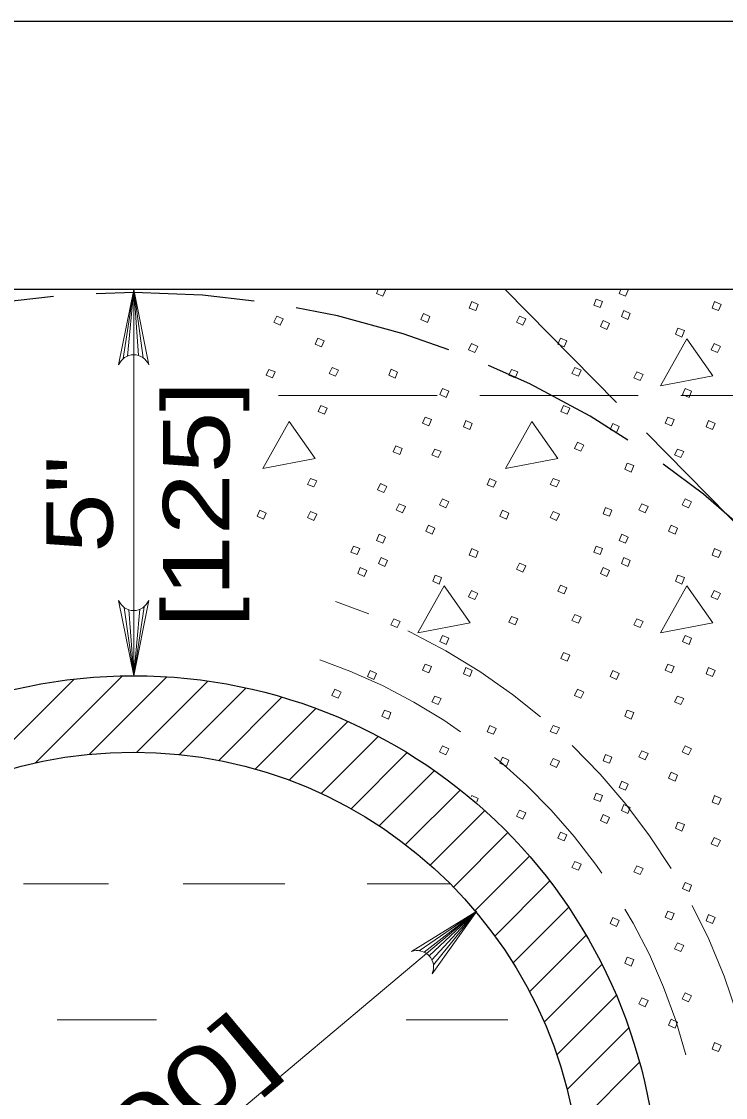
# Model space of a CAD drawing. Extents: x 1036.7 to 1070.7, y 883.9 to 905.9.
# Drawn here: x 1060.088 to 1061.74, y 889.969 to 892.494 of the extents above; entities that cross this region are included whole.
import ezdxf
from ezdxf.enums import TextEntityAlignment as Align

# ---------------------------------------------------------------- set-up
doc = ezdxf.new("R2010")
doc.units = 0
doc.header["$LTSCALE"] = 0.062
doc.linetypes.add('LONG_DASHED', pattern=[7.5, 6, -1.5])
doc.layers.add('1', color=7, linetype='Continuous', lineweight=13)

msp = doc.modelspace()

# ---------------------------------------------------------------- linework, layer by layer
at = {"layer": '1', "lineweight": 25}
for p, q in [((1062.47975, 892.494), (1058.22342, 892.494)), ((1062.47975, 891.86492), (1058.22342, 891.86492))]:
    msp.add_line(p, q, dxfattribs=at)
at = {"layer": '1'}
for p, q in [((1060.32675, 891.70283), (1060.35158, 891.86492)), ((1060.33717, 891.70892), (1060.35158, 891.86492)), ((1060.35158, 891.86492), (1060.35158, 891.54058)), ((1060.35158, 891.71175), (1060.35158, 891.86492)), ((1060.36292, 891.71017), (1060.35158, 891.86492)), ((1060.374, 891.70467), (1060.35158, 891.86492)), ((1060.35158, 890.95858), (1060.35158, 891.54058)), ((1060.32917, 891.11883), (1060.35158, 890.95858)), ((1060.37633, 891.12067), (1060.35158, 890.95858)), ((1060.34025, 891.11333), (1060.35158, 890.95858)), ((1060.36592, 891.11458), (1060.35158, 890.95858)), ((1060.35158, 891.11175), (1060.35158, 890.95858)), ((1059.96908, 890.70792), (1060.21167, 890.95058)), ((1060.12142, 890.75425), (1060.32483, 890.95767)), ((1060.24758, 890.77442), (1060.42908, 890.95592)), ((1060.35858, 890.77933), (1060.52533, 890.94608)), ((1060.459, 890.77375), (1060.615, 890.92975)), ((1060.55125, 890.76), (1060.69933, 890.90808)), ((1060.63675, 890.7395), (1060.77892, 890.88167)), ((1060.71667, 890.71333), (1060.85433, 890.851)), ((1060.7915, 890.68225), (1060.92558, 890.81633)), ((1060.86175, 890.6465), (1060.993, 890.77775)), ((1060.92775, 890.60642), (1061.057, 890.73558)), ((1060.98967, 890.56233), (1061.1175, 890.69017)), ((1061.14433, 890.67508), (1061.14525, 890.67725)), ((1061.04783, 890.5145), (1061.17483, 890.6415)), ((1061.102, 890.46275), (1061.229, 890.58967)), ((1061.1525, 890.40717), (1061.27992, 890.53467)), ((1060.09275, 890.4705), (1060.29267, 890.4705)), ((1060.46758, 890.4705), (1060.70617, 890.4705)), ((1060.8995, 890.4705), (1061.09433, 890.4705)), ((1061.19917, 890.34783), (1061.32775, 890.47642)), ((1061.24192, 890.2845), (1061.37233, 890.41492)), ((1059.55425, 889.06067), (1061.15725, 890.40575)), ((1061.02167, 890.31342), (1061.15725, 890.40575)), ((1061.03325, 890.31), (1061.15725, 890.40575)), ((1061.04508, 890.30142), (1061.15725, 890.40575)), ((1061.05158, 890.292), (1061.15725, 890.40575)), ((1061.05517, 890.28017), (1061.15725, 890.40575)), ((1061.2805, 890.21717), (1061.41317, 890.34975)), ((1061.31483, 890.14542), (1061.45025, 890.28083)), ((1061.34442, 890.069), (1061.48375, 890.20833)), ((1060.17158, 890.15083), (1060.40508, 890.15083)), ((1060.99117, 890.15083), (1061.22967, 890.15083)), ((1061.36875, 889.98733), (1061.51317, 890.13175)), ((1061.38708, 889.89967), (1061.53817, 890.05075))]:
    msp.add_line(p, q, dxfattribs=at)
at = {"layer": '1', "linetype": 'LONG_DASHED'}
for p, q in [((1061.22375, 891.86492), (1062.47975, 890.5895)), ((1062.47975, 891.61667), (1060.64108, 891.61667))]:
    msp.add_line(p, q, dxfattribs=at)
at = {"layer": '1'}
for points in [[(1060.31617, 891.68792), (1060.35158, 891.86492), (1060.387, 891.68792)], [(1060.93933, 891.86492), (1060.94233, 891.8635), (1060.93633, 891.8495), (1060.92133, 891.8555), (1060.92508, 891.86492)], [(1061.50908, 891.86492), (1061.51208, 891.8635), (1061.50608, 891.8495), (1061.49108, 891.8555), (1061.49483, 891.86492)], [(1060.387, 891.13558), (1060.35158, 890.95858), (1060.31617, 891.13558)], [(1061.14525, 890.67725), (1061.16025, 890.67025), (1061.157, 890.66267)], [(1061.0035, 890.31108), (1061.15725, 890.40575), (1061.05175, 890.25925)]]:
    msp.add_lwpolyline(points, dxfattribs=at)
for points in [[(1061.14525, 891.83658), (1061.16025, 891.82958), (1061.15425, 891.81558), (1061.13925, 891.82158)], [(1061.43717, 891.8425), (1061.45208, 891.83658), (1061.44617, 891.82258), (1061.43117, 891.82858)], [(1061.715, 891.83658), (1061.73, 891.82958), (1061.724, 891.81558), (1061.709, 891.82158)], [(1060.6875, 891.80258), (1060.7025, 891.79658), (1060.6955, 891.78158), (1060.6805, 891.78858)], [(1061.03183, 891.80842), (1061.04683, 891.80142), (1061.04083, 891.78742), (1061.02583, 891.79442)], [(1061.25725, 891.80258), (1061.27217, 891.79658), (1061.26525, 891.78158), (1061.25025, 891.78858)], [(1061.50208, 891.81558), (1061.51708, 891.80858), (1061.51108, 891.79458), (1061.49608, 891.80158)], [(1061.45308, 891.79258), (1061.46808, 891.78558), (1061.46208, 891.77158), (1061.44717, 891.77858)], [(1061.629, 891.77458), (1061.644, 891.76858), (1061.638, 891.75358), (1061.62308, 891.76058)], [(1060.78342, 891.75058), (1060.79842, 891.74458), (1060.79242, 891.73058), (1060.77742, 891.73658)], [(1061.35317, 891.75058), (1061.36817, 891.74458), (1061.36217, 891.73058), (1061.34717, 891.73658)], [(1061.65, 891.74958), (1061.58808, 891.63867), (1061.711, 891.66267)], [(1061.14425, 891.73858), (1061.15925, 891.73158), (1061.15225, 891.71758), (1061.13725, 891.72358)], [(1061.714, 891.73858), (1061.729, 891.73158), (1061.722, 891.71758), (1061.707, 891.72358)], [(1060.6685, 891.67767), (1060.6835, 891.67167), (1060.6775, 891.65767), (1060.6625, 891.66367)], [(1060.81742, 891.68167), (1060.83242, 891.67567), (1060.82542, 891.66167), (1060.81042, 891.66767)], [(1060.95608, 891.67775), (1060.97108, 891.67075), (1060.96508, 891.65675), (1060.95008, 891.66375)], [(1061.23825, 891.67767), (1061.25325, 891.67167), (1061.24725, 891.65767), (1061.23225, 891.66367)], [(1061.38717, 891.68167), (1061.40217, 891.67567), (1061.39517, 891.66167), (1061.38017, 891.66767)], [(1061.53208, 891.67167), (1061.54708, 891.66567), (1061.54008, 891.65167), (1061.52508, 891.65767)], [(1061.07633, 891.63267), (1061.09133, 891.62667), (1061.08533, 891.61167), (1061.07033, 891.61867)], [(1061.646, 891.63267), (1061.661, 891.62667), (1061.655, 891.61167), (1061.64, 891.61867)], [(1060.79042, 891.59267), (1060.80542, 891.58667), (1060.79942, 891.57267), (1060.78442, 891.57867)], [(1061.36017, 891.59267), (1061.37517, 891.58667), (1061.36917, 891.57267), (1061.35417, 891.57867)], [(1060.7165, 891.55567), (1060.6545, 891.44475), (1060.77742, 891.46875)], [(1061.03533, 891.56567), (1061.05033, 891.55967), (1061.04433, 891.54475), (1061.02933, 891.55167)], [(1061.13125, 891.55767), (1061.14625, 891.55067), (1061.14025, 891.53675), (1061.12525, 891.54275)], [(1061.28617, 891.55567), (1061.22425, 891.44475), (1061.34717, 891.46875)], [(1061.47608, 891.55067), (1061.49108, 891.54375), (1061.48508, 891.52975), (1061.47008, 891.53675)], [(1061.60508, 891.56567), (1061.62008, 891.55967), (1061.61408, 891.54475), (1061.59908, 891.55167)], [(1061.701, 891.55767), (1061.716, 891.55067), (1061.71, 891.53675), (1061.695, 891.54275)], [(1060.96692, 891.498), (1060.98192, 891.492), (1060.97592, 891.47808), (1060.96092, 891.48408)], [(1061.39317, 891.50675), (1061.40817, 891.49975), (1061.40117, 891.48575), (1061.38617, 891.49175)], [(1061.05833, 891.49075), (1061.07333, 891.48475), (1061.06633, 891.47075), (1061.05133, 891.47675)], [(1061.628, 891.49075), (1061.643, 891.48475), (1061.636, 891.47075), (1061.62108, 891.47675)], [(1061.51008, 891.45775), (1061.52508, 891.45175), (1061.51908, 891.43675), (1061.50408, 891.44375)], [(1060.76642, 891.42175), (1060.78142, 891.41575), (1060.77442, 891.40183), (1060.75942, 891.40775)], [(1061.18725, 891.42175), (1061.20225, 891.41475), (1061.19625, 891.40083), (1061.18125, 891.40675)], [(1061.33617, 891.42175), (1061.35117, 891.41575), (1061.34417, 891.40183), (1061.32917, 891.40775)], [(1060.93058, 891.40983), (1060.94558, 891.40283), (1060.93858, 891.38883), (1060.92358, 891.39483)], [(1061.07633, 891.37383), (1061.09133, 891.36683), (1061.08433, 891.35283), (1061.06933, 891.35983)], [(1061.646, 891.37383), (1061.661, 891.36683), (1061.654, 891.35283), (1061.639, 891.35983)], [(1060.6475, 891.34683), (1060.6625, 891.33983), (1060.6565, 891.32583), (1060.6415, 891.33283)], [(1060.97433, 891.36183), (1060.98933, 891.35583), (1060.98233, 891.34083), (1060.96733, 891.34783)], [(1061.21725, 891.34683), (1061.23225, 891.33983), (1061.22625, 891.32583), (1061.21125, 891.33283)], [(1061.45908, 891.35383), (1061.47408, 891.34683), (1061.46808, 891.33283), (1061.45308, 891.33883)], [(1061.54408, 891.36183), (1061.55908, 891.35583), (1061.55208, 891.34083), (1061.53708, 891.34783)], [(1060.76642, 891.34383), (1060.78142, 891.33783), (1060.77442, 891.32283), (1060.75942, 891.32983)], [(1061.33617, 891.34383), (1061.35117, 891.33783), (1061.34417, 891.32283), (1061.32917, 891.32983)], [(1061.04333, 891.31183), (1061.05833, 891.30483), (1061.05233, 891.29083), (1061.03733, 891.29783)], [(1061.61308, 891.31183), (1061.628, 891.30483), (1061.62208, 891.29083), (1061.60708, 891.29783)], [(1060.92733, 891.29083), (1060.94233, 891.28383), (1060.93633, 891.26983), (1060.92133, 891.27583)], [(1061.49708, 891.29083), (1061.51208, 891.28383), (1061.50608, 891.26983), (1061.49108, 891.27583)], [(1060.86742, 891.26283), (1060.88242, 891.25692), (1060.87642, 891.24292), (1060.86142, 891.24892)], [(1061.14525, 891.25692), (1061.16025, 891.24992), (1061.15425, 891.23592), (1061.13925, 891.24192)], [(1061.43717, 891.26283), (1061.45208, 891.25692), (1061.44617, 891.24292), (1061.43117, 891.24892)], [(1061.715, 891.25692), (1061.73, 891.24992), (1061.724, 891.23592), (1061.709, 891.24192)], [(1060.93233, 891.23592), (1060.94733, 891.22892), (1060.94133, 891.21492), (1060.92633, 891.22192)], [(1061.25725, 891.22292), (1061.27217, 891.21692), (1061.26525, 891.20192), (1061.25025, 891.20892)], [(1061.50208, 891.23592), (1061.51708, 891.22892), (1061.51108, 891.21492), (1061.49608, 891.22192)], [(1060.88342, 891.21292), (1060.89842, 891.20592), (1060.89242, 891.19192), (1060.87742, 891.19892)], [(1061.05933, 891.19492), (1061.07433, 891.18892), (1061.06833, 891.17392), (1061.05333, 891.18092)], [(1061.45308, 891.21292), (1061.46808, 891.20592), (1061.46208, 891.19192), (1061.44717, 891.19892)], [(1061.629, 891.19492), (1061.644, 891.18892), (1061.638, 891.17392), (1061.62308, 891.18092)], [(1061.08033, 891.16992), (1061.01833, 891.059), (1061.14125, 891.083)], [(1061.35317, 891.17092), (1061.36817, 891.16492), (1061.36217, 891.15092), (1061.34717, 891.15692)], [(1061.65, 891.16992), (1061.58808, 891.059), (1061.711, 891.083)], [(1061.14425, 891.15892), (1061.15925, 891.15192), (1061.15225, 891.13792), (1061.13725, 891.14392)], [(1061.714, 891.15892), (1061.729, 891.15192), (1061.722, 891.13792), (1061.707, 891.14392)], [(1060.96233, 891.092), (1060.97733, 891.086), (1060.97033, 891.072), (1060.95533, 891.078)], [(1061.23825, 891.098), (1061.25325, 891.092), (1061.24725, 891.078), (1061.23225, 891.084)], [(1061.38717, 891.102), (1061.40217, 891.096), (1061.39517, 891.082), (1061.38017, 891.088)], [(1061.53208, 891.092), (1061.54708, 891.086), (1061.54008, 891.072), (1061.52508, 891.078)], [(1061.07633, 891.053), (1061.09133, 891.047), (1061.08533, 891.032), (1061.07033, 891.039)], [(1061.646, 891.053), (1061.661, 891.047), (1061.655, 891.032), (1061.64, 891.039)], [(1061.36017, 891.013), (1061.37517, 891.007), (1061.36917, 890.993), (1061.35417, 890.999)], [(1060.90642, 890.971), (1060.92133, 890.96408), (1060.91542, 890.95008), (1060.90042, 890.95708)], [(1061.03533, 890.986), (1061.05033, 890.98), (1061.04433, 890.96508), (1061.02933, 890.972)], [(1061.13125, 890.978), (1061.14625, 890.971), (1061.14025, 890.95708), (1061.12525, 890.96308)], [(1061.47608, 890.971), (1061.49108, 890.96408), (1061.48508, 890.95008), (1061.47008, 890.95708)], [(1061.60508, 890.986), (1061.62008, 890.98), (1061.61408, 890.96508), (1061.59908, 890.972)], [(1061.701, 890.978), (1061.716, 890.971), (1061.71, 890.95708), (1061.695, 890.96308)], [(1060.82342, 890.92708), (1060.83842, 890.92008), (1060.83142, 890.90608), (1060.81642, 890.91208)], [(1061.39317, 890.92708), (1061.40817, 890.92008), (1061.40117, 890.90608), (1061.38617, 890.91208)], [(1061.05833, 890.91108), (1061.07333, 890.90508), (1061.06633, 890.89108), (1061.05133, 890.89708)], [(1061.628, 890.91108), (1061.643, 890.90508), (1061.636, 890.89108), (1061.62108, 890.89708)], [(1060.94033, 890.87808), (1060.95533, 890.87208), (1060.94933, 890.85708), (1060.93433, 890.86408)], [(1061.51008, 890.87808), (1061.52508, 890.87208), (1061.51908, 890.85708), (1061.50408, 890.86408)], [(1061.18725, 890.84208), (1061.20225, 890.83508), (1061.19625, 890.82117), (1061.18125, 890.82708)], [(1061.33617, 890.84208), (1061.35117, 890.83608), (1061.34417, 890.82217), (1061.32917, 890.82808)], [(1061.07633, 890.79417), (1061.09133, 890.78717), (1061.08433, 890.77317), (1061.06933, 890.78017)], [(1061.646, 890.79417), (1061.661, 890.78717), (1061.654, 890.77317), (1061.639, 890.78017)], [(1061.21725, 890.76717), (1061.23225, 890.76017), (1061.22625, 890.74617), (1061.21125, 890.75317)], [(1061.33617, 890.76417), (1061.35117, 890.75817), (1061.34417, 890.74317), (1061.32917, 890.75017)], [(1061.45908, 890.77417), (1061.47408, 890.76717), (1061.46808, 890.75317), (1061.45308, 890.75917)], [(1061.54408, 890.78217), (1061.55908, 890.77617), (1061.55208, 890.76117), (1061.53708, 890.76817)], [(1061.61308, 890.73217), (1061.628, 890.72517), (1061.62208, 890.71117), (1061.60708, 890.71817)], [(1061.49708, 890.71117), (1061.51208, 890.70417), (1061.50608, 890.69017), (1061.49108, 890.69617)], [(1061.43717, 890.68317), (1061.45208, 890.67725), (1061.44617, 890.66325), (1061.43117, 890.66925)], [(1061.715, 890.67725), (1061.73, 890.67025), (1061.724, 890.65625), (1061.709, 890.66225)], [(1061.25725, 890.64325), (1061.27217, 890.63725), (1061.26525, 890.62225), (1061.25025, 890.62925)], [(1061.50208, 890.65625), (1061.51708, 890.64925), (1061.51108, 890.63525), (1061.49608, 890.64225)], [(1061.45308, 890.63325), (1061.46808, 890.62625), (1061.46208, 890.61225), (1061.44717, 890.61925)], [(1061.629, 890.61525), (1061.644, 890.60925), (1061.638, 890.59425), (1061.62308, 890.60125)], [(1061.35317, 890.59125), (1061.36817, 890.58525), (1061.36217, 890.57125), (1061.34717, 890.57725)], [(1061.714, 890.57925), (1061.729, 890.57225), (1061.722, 890.55825), (1061.707, 890.56425)], [(1061.38717, 890.52233), (1061.40217, 890.51633), (1061.39517, 890.50233), (1061.38017, 890.50833)], [(1061.53208, 890.51233), (1061.54708, 890.50633), (1061.54008, 890.49233), (1061.52508, 890.49833)], [(1061.646, 890.47333), (1061.661, 890.46733), (1061.655, 890.45233), (1061.64, 890.45933)], [(1061.47608, 890.39133), (1061.49108, 890.38442), (1061.48508, 890.37042), (1061.47008, 890.37742)], [(1061.60508, 890.40633), (1061.62008, 890.40033), (1061.61408, 890.38542), (1061.59908, 890.39233)], [(1061.701, 890.39833), (1061.716, 890.39133), (1061.71, 890.37742), (1061.695, 890.38342)], [(1061.628, 890.33142), (1061.643, 890.32542), (1061.636, 890.31142), (1061.62108, 890.31742)], [(1061.51008, 890.29842), (1061.52508, 890.29242), (1061.51908, 890.27742), (1061.50408, 890.28442)], [(1061.646, 890.2145), (1061.661, 890.2075), (1061.654, 890.1935), (1061.639, 890.2005)], [(1061.54408, 890.2025), (1061.55908, 890.1965), (1061.55208, 890.1815), (1061.53708, 890.1885)], [(1061.61308, 890.1525), (1061.628, 890.1455), (1061.62208, 890.1315), (1061.60708, 890.1385)], [(1061.715, 890.09758), (1061.73, 890.09058), (1061.724, 890.07658), (1061.709, 890.08258)]]:
    msp.add_lwpolyline(points, close=True, dxfattribs=at)
for centre, start, end in [((1060.3516, 891.67365), 22.08782, 157.91395), ((1060.35152, 891.14984), 202.08782, 337.91395), ((1061.01721, 890.2754), 335.02041, 110.84653)]:
    msp.add_arc(centre, 0.0382, start, end, dxfattribs=at)
at = {"layer": '1', "linetype": 'LONG_DASHED', "lineweight": 25}
msp.add_ellipse((1060.35006, 889.72842), major_axis=(2.1297, 0), ratio=0.999895, start_param=3.2863203, end_param=8.1610756, dxfattribs=at)
at = {"layer": '1', "linetype": 'LONG_DASHED'}
for major_axis, start_param, end_param in [((1.48321, 0), 0.2336349, 1.2445444), ((1.34164, 0), 0.2565818, 1.2445369)]:
    msp.add_ellipse((1060.35006, 889.72842), major_axis=major_axis, ratio=0.999895, start_param=start_param, end_param=end_param, dxfattribs=at)
at = {"layer": '1', "lineweight": 25}
for centre, major_axis in [((1060.35156, 889.72842), (1.23026, 0)), ((1060.35006, 889.72842), (1.05107, 0))]:
    msp.add_ellipse(centre, major_axis=major_axis, ratio=0.999895, dxfattribs=at)

# ---------------------------------------------------------------- texts
at = {"layer": '1'}
for s, width, p in [('[125]', 1.25, (1060.57625, 891.36117)), ('5"', 1.2, (1060.30225, 891.36121))]:
    msp.add_text(s, height=0.156, rotation=90, dxfattribs=dict(at, width=width)).set_placement(p, align=Align.CENTER)
at = {"layer": '1', "width": 1.45}
msp.add_text('12" [300]', height=0.156, rotation=40, dxfattribs=at).set_placement((1059.77125, 889.28575))

doc.saveas('drawing.dxf')
